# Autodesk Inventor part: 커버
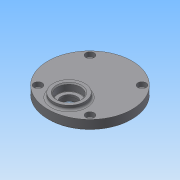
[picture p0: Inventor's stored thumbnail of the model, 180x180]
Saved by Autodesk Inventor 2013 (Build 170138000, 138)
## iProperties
Created: 2014-12
Part Number: 커버
Material: Generic
Document SubType Name: Modeling
Designer: Administrator
Density: 1 g/cm^3
Author: Administrator
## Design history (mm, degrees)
sketch "Sketch1" dims "d0" = 80
  geometry: L1 (0, 0)-(0, 40); 2 further points
  constraints: 2 end point, 1 coincident, 1 vertical, 1 vertical alignment, 2 other
  dimensions: "d1" = 45 deg dimension on point (0, 0) L1.end point (-24.749, 24.749); "d3" = 35 distance of point (0, 0) point (-24.749, 24.749)
extrude "Extrusion1" new body sketch "Sketch1" distance "d4" = 9; taper "d5" = 0 deg
hole "Hole1" sketch "Sketch1" diameter "d6" = 4.5; stored, may be unused: countersink angle "d10" = 90 deg, drill point angle "d12" = 118 deg; dims "d7" = 6, "d8" = 8, "d9" = 4.4, "d11" = 8
pattern_circular "Circular Pattern1" dims angle "d14" = 360 deg
sketch "Sketch2"
  geometry: C1 r 40 at (0, 0) reference; C2 r 15 at (0, -20)
  constraints: 1 centre point, 1 vertical alignment
  dimensions: "d16" = 30 diameter of C2; "d17" = 20 distance of C2.centre C1.centre
extrude "Extrusion2" join sketch "Sketch2" distance "d18" = 4; taper "d19" = 0 deg
sketch "Sketch3"
  geometry: C1 r 40 at (0, 0) reference; C2 r 14 at (0, 11); C3 r 14 at (0, -20)
  constraints: 2 centre point, 2 vertical alignment
  dimensions: "d20" = 28 diameter of C2; "d21" = 28 diameter of C3; "d22" = 11 distance of C1.centre C2.centre; "d23" = 20 distance of C3.centre C1.centre
extrude "Extrusion3" join sketch "Sketch3" distance "d24" = 3; taper "d25" = 0 deg
sketch "Sketch4"
  geometry: C1 r 14 at (0, 0) reference; C2 r 11 at (0, 0); C3 r 14 at (0, -31) reference; C4 r 11 at (0, -31); 1 further point
  constraints: 2 centre point, 2 coincident
  dimensions: "d26" = 22 diameter of C2; "d27" = 22 diameter of C4
extrude "Extrusion4" cut sketch "Sketch4" distance "d28" = 7; taper "d29" = 0 deg
sketch "Sketch5"
  geometry: C1 r 9 at (0, 0); C2 r 11 at (0, -31) reference; C3 r 7.5 at (0, -31); 2 further points
  constraints: 2 centre point, 2 coincident, 1 vertical alignment
  dimensions: "d30" = 18 diameter of C1; "d31" = 15 diameter of C3
  node "Projected Loop1"
extrude "Extrusion5" cut sketch "Sketch5" distance "d32" = 1; taper "d33" = 0 deg
extrude "Extrusion6" cut sketch "Sketch5" distance "d34" = 2; taper "d35" = 0 deg
sketch "Sketch6"
  geometry: C1 r 15 at (0, 0) reference; C2 r 11 at (0, 0); 1 further point
  constraints: 1 centre point, 1 coincident
  dimensions: "d36" = 22 diameter of C2
extrude "Extrusion7" cut sketch "Sketch6" distance "d28" = 7; distance "d37" = 7; taper "d38" = 0 deg
chamfer "Chamfer1" distance "d39" = 1; stored, may be unused: second distance "d40" = 2, angle "d41" = 45 deg
fillet "Fillet1" dims "d42" = 2, "d43" = 0.3
body "Solid1"
